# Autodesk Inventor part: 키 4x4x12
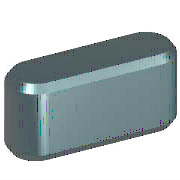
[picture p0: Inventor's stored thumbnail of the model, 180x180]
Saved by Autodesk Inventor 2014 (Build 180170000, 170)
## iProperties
IsCustomPart: 1
Created: 2012-02
Part Number: 키 4x4x12
Material: 강철, 연강
Description: 키 및 해당 키홈
Document SubType Name: Modeling
Standard: KS B 1311
Designer: mduedu
Standards Organization: KS
Language: ko-KR
Size Designation: 4 x 4 x 12
Categories: <MemberInstance><Categories><Category DisplayName="샤프트 부품" InternalName="7f7aeb1f-a693-4053-b835-cee3144e0d98" Mnemonic="SHFT"><Category DisplayName="키" Interna
Density: 1 g/cm^3
Appearance: 노란색
Author: mduedu
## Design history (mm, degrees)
workplane "Work Plane1"
workplane "Work Plane2"
sketch "스케치1"
  geometry: L1 (2, 2)-(10, 2); L2 (10, -2)-(2, -2); L3 (0, 9.4)-(0, -7.4) reference; L4 (-5, 0)-(30, 0) reference; L5 (12, 0)-(12, 7); A1 r 2 centre (2, 0) between (2, 2) and (2, -2); A2 r 2 centre (10, 0) between (10, -2) and (10, 2)
  constraints: 6 end point, 5 point on circle, 4 tangent, 3 point on line, 2 centre point, 1 horizontal, 1 parallel, 1 perpendicular
  dimensions: "d0" = 2 radius of A1 (= 0.5 x PB); "d13" = 2 radius of A2 (= 0.5 x PB); "d14" = 12 distance between parallel lines of L5 L3 (= NLG)
extrude "본체1" new body sketch "스케치1" taper "d3" = 0 deg; stored distance "d4" = 10
workplane "Work Plane3"
body "Solid1"
chamfer "모따기1" distance "d8" = 0.25 (= PHH); stored, may be unused: second distance "d9" = 0.25 (= PHH), angle "d15" = 45 deg
other parameters: "d1" = -2.5 (= -PNT), "d2" = 1.5 (= PH - PNT), "NLG" = 12 [user parameter; used in 3 equation terms], "PB" = 4 [user parameter; used in 2 equation terms], "PNT" = 2.5 [user parameter; used in 2 equation terms], "PH" = 4 [user parameter; used in 1 equation term], "PHH" = 0.25 [user parameter; used in 2 equation terms], "d10" = 0, "d16" = 0, "d17" = 0, "d18" = 0, "PLB2" = 12 (= NLG) [user parameter], "WDMAX" = 12 [user parameter], "PLB1" = 12 (= NLG) [user parameter], "RR" = 0.08 [user parameter], "PUEB" = 1.8 [user parameter]
